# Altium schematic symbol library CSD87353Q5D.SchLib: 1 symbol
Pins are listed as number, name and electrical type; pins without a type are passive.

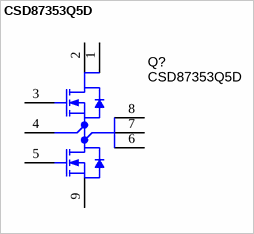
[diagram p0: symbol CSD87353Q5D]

## CSD87353Q5D
designator Q?
Manufacturer: Texas Instruments; Alternate Manufacturer: None; CompType: MOSFET; U/M: EA; ChType: N
pins: 1 VIN, 2 VIN, 3 TG, 4 TGR, 5 BG, 6 VSW, 7 VSW, 8 VSW, 9 PGND
1 alternate drawing of the same symbol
